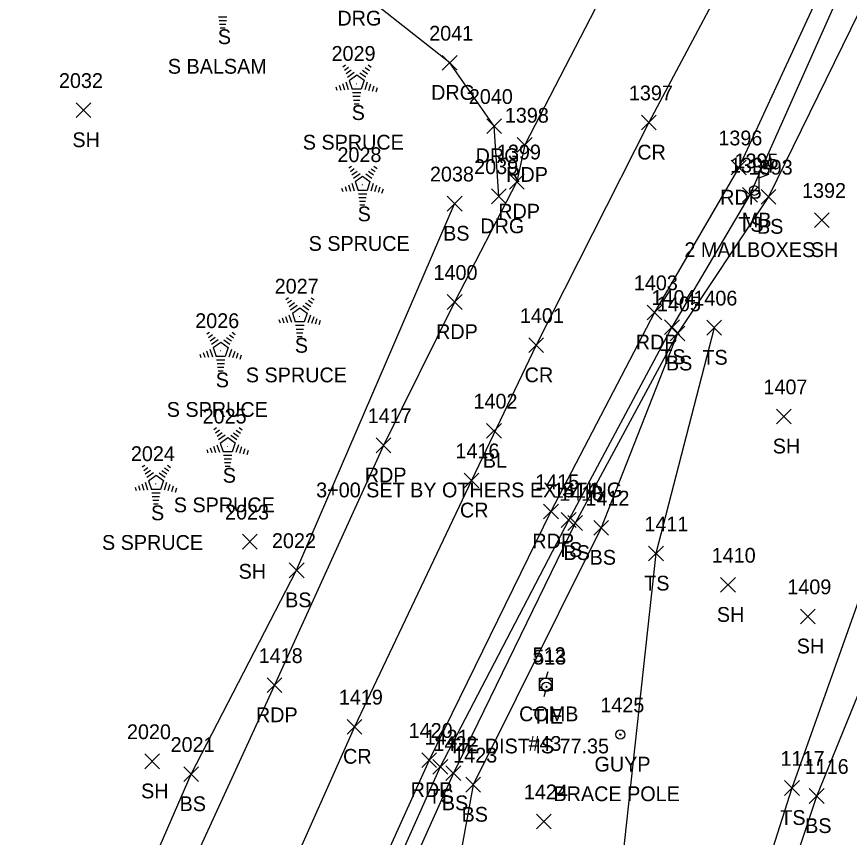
# Model space of a CAD drawing. Extents: x 1885914 to 1887218, y 756253 to 760620.
# Drawn here: x 1886470.3 to 1886583, y 759954.5 to 760065.4 of the extents above; entities that cross this region are included whole.
import ezdxf

# ---------------------------------------------------------------- set-up
doc = ezdxf.new("R2010")
doc.units = 0
for name, color, linetype in [('C_A', 7, 'Continuous'), ('C_C', 7, 'Continuous'), ('C_I', 7, 'Continuous'), ('C_TIC', 7, 'Continuous'), ('CBP', 7, 'Continuous'), ('L_A', 7, 'Continuous'), ('L_C', 7, 'Continuous'), ('L_I', 7, 'Continuous'), ('L_TIC', 7, 'Continuous'), ('LELB', 7, 'Continuous'), ('LMB', 7, 'Continuous'), ('LTC', 7, 'Continuous'), ('P_A', 7, 'Continuous'), ('P_I', 7, 'Continuous'), ('P_TIC', 7, 'Continuous'), ('PET', 7, 'Continuous'), ('PRC', 7, 'Continuous'), ('R_A', 7, 'Continuous'), ('R_I', 7, 'Continuous'), ('R_TIC', 7, 'Continuous'), ('RDG', 7, 'Continuous'), ('U_A', 7, 'Continuous'), ('U_C', 7, 'Continuous'), ('U_I', 7, 'Continuous'), ('UP', 7, 'Continuous'), ('UPGW', 7, 'Continuous')]:
    doc.layers.add(name, color=color, linetype=linetype)

msp = doc.modelspace()

# ---------------------------------------------------------------- linework, layer by layer
at = {"layer": 'C_TIC'}
for points in [[(1886533.9, 760008.44), (1886535.9, 760010.44)], [(1886535.9, 760008.44), (1886533.9, 760010.44)]]:
    msp.add_lwpolyline(points, dxfattribs=at)
at = {"layer": 'CBP'}
for radius in [0.625, 0.0833]:
    msp.add_circle((1886542, 759974.83), radius, dxfattribs=at)
at = {"layer": 'L_TIC'}
for points in [[(1886478.39, 760051.78), (1886480.39, 760053.78)], [(1886480.39, 760051.78), (1886478.39, 760053.78)], [(1886568.53, 760040.34), (1886570.53, 760042.34)], [(1886570.53, 760040.34), (1886568.53, 760042.34)], [(1886571.04, 760040.07), (1886573.04, 760042.07)], [(1886573.04, 760040.07), (1886571.04, 760042.07)], [(1886528.58, 760039.14), (1886530.58, 760041.14)], [(1886530.58, 760039.14), (1886528.58, 760041.14)], [(1886578.26, 760036.92), (1886580.26, 760038.92)], [(1886580.26, 760036.92), (1886578.26, 760038.92)], [(1886557.98, 760022.45), (1886559.98, 760024.45)], [(1886559.98, 760022.45), (1886557.98, 760024.45)], [(1886558.72, 760021.59), (1886560.72, 760023.59)], [(1886560.72, 760021.59), (1886558.72, 760023.59)], [(1886558.72, 760021.59), (1886560.72, 760023.59)], [(1886560.72, 760021.59), (1886558.72, 760023.59)], [(1886563.69, 760022.37), (1886565.69, 760024.37)], [(1886565.69, 760022.37), (1886563.69, 760024.37)], [(1886573.12, 760010.37), (1886575.12, 760012.37)], [(1886575.12, 760010.37), (1886573.12, 760012.37)], [(1886544.01, 759996.38), (1886546.01, 759998.38)], [(1886546.01, 759996.38), (1886544.01, 759998.38)], [(1886544.87, 759995.97), (1886546.87, 759997.97)], [(1886546.87, 759995.97), (1886544.87, 759997.97)], [(1886548.4, 759995.33), (1886550.4, 759997.33)], [(1886550.4, 759995.33), (1886548.4, 759997.33)], [(1886500.87, 759993.44), (1886502.87, 759995.44)], [(1886502.87, 759993.44), (1886500.87, 759995.44)], [(1886555.81, 759991.84), (1886557.81, 759993.84)], [(1886557.81, 759991.84), (1886555.81, 759993.84)], [(1886507.21, 759989.58), (1886509.21, 759991.58)], [(1886509.21, 759989.58), (1886507.21, 759991.58)], [(1886565.56, 759987.61), (1886567.56, 759989.61)], [(1886567.56, 759987.61), (1886565.56, 759989.61)], [(1886576.36, 759983.34), (1886578.36, 759985.34)], [(1886578.36, 759983.34), (1886576.36, 759985.34)], [(1886487.68, 759963.75), (1886489.68, 759965.75)], [(1886489.68, 759963.75), (1886487.68, 759965.75)], [(1886526.64, 759963.02), (1886528.64, 759965.02)], [(1886528.64, 759963.02), (1886526.64, 759965.02)], [(1886492.94, 759962.02), (1886494.94, 759964.02)], [(1886494.94, 759962.02), (1886492.94, 759964.02)], [(1886528.41, 759962.14), (1886530.41, 759964.14)], [(1886530.41, 759962.14), (1886528.41, 759964.14)], [(1886531.08, 759960.59), (1886533.08, 759962.59)], [(1886533.08, 759960.59), (1886531.08, 759962.59)], [(1886574.22, 759960.15), (1886576.22, 759962.15)], [(1886576.22, 759960.15), (1886574.22, 759962.15)], [(1886577.55, 759959.06), (1886579.55, 759961.06)], [(1886579.55, 759959.06), (1886577.55, 759961.06)], [(1886540.64, 759955.62), (1886542.64, 759957.62)], [(1886542.64, 759955.62), (1886540.64, 759957.62)]]:
    msp.add_lwpolyline(points, dxfattribs=at)
at = {"layer": 'LELB'}
for points in [[(1886725.27, 760338.09), (1886712.33, 760310.28), (1886698.46, 760286.41), (1886683.25, 760252.31), (1886665.56, 760220.6), (1886649.26, 760186.3), (1886631.93, 760155.48), (1886614.95, 760123.77), (1886599.48, 760094.94), (1886586.46, 760070.53), (1886572.04, 760041.07), (1886559.72, 760022.59), (1886545.87, 759996.97), (1886529.41, 759963.14), (1886510.6, 759921.25), (1886501.24, 759900.36), (1886492.69, 759872.91), (1886485.39, 759846.95), (1886480.56, 759824.59), (1886476.3, 759808.27), (1886477.13, 759795.21)], [(1886722.34, 760338.16), (1886708.2, 760311.94), (1886695.5, 760287.88), (1886679.14, 760254.71), (1886661.55, 760221.54), (1886644.91, 760188.52), (1886628.61, 760157.02), (1886611.22, 760125.9), (1886595.57, 760097.05), (1886583.24, 760072.24), (1886569.53, 760041.34), (1886558.98, 760023.45), (1886545.01, 759997.38), (1886527.64, 759964.02), (1886508.85, 759921.99)], [(1886569.47, 759932.79), (1886578.55, 759960.06), (1886589.25, 759986.28), (1886598.57, 760012.52), (1886604.77, 760034.06), (1886609.07, 760058.69), (1886625.15, 760085.1), (1886640.42, 760091.38), (1886649.45, 760109.89), (1886661.77, 760128.12), (1886683.78, 760144.02), (1886702.73, 760156.3), (1886717, 760162.7), (1886740.68, 760172.2), (1886760.93, 760185.46), (1886776.22, 760178.86), (1886795.79, 760185.28), (1886813.44, 760184.92), (1886834.73, 760176.46), (1886849.11, 760176.99)], [(1886572.3, 759803.95), (1886568.6, 759823.21), (1886564.73, 759854.7), (1886563.87, 759883.9), (1886566.65, 759905.78), (1886566.1, 759932.48), (1886575.22, 759961.15), (1886584.71, 759987.76), (1886595.18, 760013.31), (1886601.19, 760034.22), (1886605.14, 760059.41), (1886622.97, 760086.15), (1886635.93, 760094.98), (1886646.75, 760112.81), (1886658.85, 760130.9), (1886680.3, 760148.52), (1886699.66, 760159.95), (1886715.31, 760165.82), (1886739.18, 760176.38)], [(1886435.82, 759833.71), (1886443.92, 759843.16), (1886452.31, 759861.14), (1886457.66, 759877.13), (1886463.57, 759888.48), (1886474.59, 759918.53), (1886493.94, 759963.02), (1886508.21, 759990.58), (1886529.58, 760040.14)], [(1886564.69, 760023.37), (1886556.81, 759992.84), (1886551.99, 759948.71), (1886542, 759918.15), (1886528.59, 759884.81), (1886523.26, 759869.7), (1886515.99, 759841.78), (1886514.24, 759821.96)], [(1886559.72, 760022.59), (1886549.4, 759996.33), (1886532.08, 759961.59), (1886524, 759917.34), (1886512.94, 759920.8), (1886504.17, 759899.59), (1886494.61, 759872.13), (1886487.33, 759846.58), (1886481.7, 759824.1), (1886477.83, 759807.91), (1886479.96, 759798.66)]]:
    msp.add_lwpolyline(points, dxfattribs=at)
at = {"layer": 'LMB'}
for p, q in [((1886570.77, 760044.52), (1886572.06, 760044.14)), ((1886570.78, 760041.93), (1886570.77, 760044.52)), ((1886570.77, 760043.62), (1886572.06, 760044.13)), ((1886570.12, 760041.92), (1886570.12, 760041.92))]:
    msp.add_line(p, q, dxfattribs=at)
msp.add_circle((1886570.12, 760041.92), 0.656, dxfattribs=at)
at = {"layer": 'LTC'}
for p, q in [((1886498.79, 760065.37), (1886497.65, 760065.37)), ((1886498.71, 760064.87), (1886497.72, 760064.87)), ((1886498.62, 760064.37), (1886497.79, 760064.37)), ((1886498.54, 760063.87), (1886497.86, 760063.87)), ((1886514.47, 760058.66), (1886514.83, 760058.92)), ((1886514.68, 760058.19), (1886515.21, 760058.58)), ((1886517.5, 760058.55), (1886518.05, 760058.15)), ((1886517.87, 760058.9), (1886518.29, 760058.59)), ((1886514.89, 760057.73), (1886515.6, 760058.24)), ((1886515.1, 760057.26), (1886515.98, 760057.9)), ((1886515.33, 760056.81), (1886516.34, 760057.54)), ((1886516.34, 760057.54), (1886517.34, 760056.82)), ((1886516.76, 760057.85), (1886517.57, 760057.27)), ((1886517.13, 760058.2), (1886517.81, 760057.71)), ((1886513.96, 760056.15), (1886514.17, 760055.5)), ((1886514.42, 760056.37), (1886514.69, 760055.54)), ((1886514.87, 760056.59), (1886515.2, 760055.57)), ((1886515.33, 760056.81), (1886515.71, 760055.61)), ((1886517.34, 760056.82), (1886516.95, 760055.61)), ((1886517.77, 760056.55), (1886517.44, 760055.51)), ((1886518.22, 760056.29), (1886517.93, 760055.41)), ((1886518.66, 760056.04), (1886518.43, 760055.32)), ((1886513.51, 760055.94), (1886513.66, 760055.47)), ((1886516.95, 760055.61), (1886515.71, 760055.61)), ((1886516.91, 760055.11), (1886515.76, 760055.11)), ((1886519.11, 760055.79), (1886518.92, 760055.22)), ((1886516.82, 760054.61), (1886515.83, 760054.61)), ((1886516.74, 760054.11), (1886515.91, 760054.11)), ((1886516.66, 760053.61), (1886515.98, 760053.61)), ((1886515.27, 760044.97), (1886515.62, 760045.23)), ((1886515.48, 760044.51), (1886516.01, 760044.89)), ((1886518.3, 760044.86), (1886518.85, 760044.47)), ((1886518.67, 760045.21), (1886519.09, 760044.91)), ((1886515.69, 760044.04), (1886516.39, 760044.55)), ((1886515.9, 760043.58), (1886516.78, 760044.21)), ((1886516.12, 760043.12), (1886517.13, 760043.85)), ((1886517.13, 760043.85), (1886518.13, 760043.13)), ((1886517.55, 760044.17), (1886518.36, 760043.58)), ((1886517.92, 760044.52), (1886518.6, 760044.02)), ((1886515.21, 760042.68), (1886515.48, 760041.85)), ((1886515.67, 760042.9), (1886516, 760041.88)), ((1886516.12, 760043.12), (1886516.51, 760041.93)), ((1886518.13, 760043.13), (1886517.74, 760041.93)), ((1886518.57, 760042.86), (1886518.23, 760041.82)), ((1886519.01, 760042.61), (1886518.73, 760041.72)), ((1886514.3, 760042.25), (1886514.45, 760041.78)), ((1886514.76, 760042.47), (1886514.97, 760041.82)), ((1886517.74, 760041.93), (1886516.51, 760041.93)), ((1886517.7, 760041.43), (1886516.56, 760041.43)), ((1886519.46, 760042.36), (1886519.22, 760041.63)), ((1886519.9, 760042.11), (1886519.71, 760041.53)), ((1886517.62, 760040.93), (1886516.63, 760040.93)), ((1886517.53, 760040.43), (1886516.7, 760040.43)), ((1886517.45, 760039.93), (1886516.77, 760039.93)), ((1886506.77, 760027.19), (1886507.13, 760027.45)), ((1886506.98, 760026.73), (1886507.51, 760027.11)), ((1886507.19, 760026.26), (1886507.9, 760026.77)), ((1886509.43, 760026.74), (1886510.11, 760026.24)), ((1886509.8, 760027.09), (1886510.35, 760026.69)), ((1886510.17, 760027.43), (1886510.59, 760027.13)), ((1886507.4, 760025.8), (1886508.28, 760026.44)), ((1886507.63, 760025.34), (1886508.64, 760026.08)), ((1886508.64, 760026.08), (1886509.64, 760025.35)), ((1886509.06, 760026.39), (1886509.87, 760025.8)), ((1886506.26, 760024.69), (1886506.47, 760024.04)), ((1886506.72, 760024.91), (1886506.99, 760024.07)), ((1886507.17, 760025.12), (1886507.5, 760024.1)), ((1886507.63, 760025.34), (1886508.01, 760024.15)), ((1886509.64, 760025.35), (1886509.25, 760024.15)), ((1886510.07, 760025.08), (1886509.74, 760024.04)), ((1886510.52, 760024.83), (1886510.23, 760023.95)), ((1886510.96, 760024.58), (1886510.73, 760023.85)), ((1886505.81, 760024.47), (1886505.96, 760024.01)), ((1886509.25, 760024.15), (1886508.01, 760024.15)), ((1886509.21, 760023.65), (1886508.06, 760023.65)), ((1886511.41, 760024.33), (1886511.22, 760023.76)), ((1886496.08, 760022.53), (1886496.44, 760022.79)), ((1886496.29, 760022.06), (1886496.82, 760022.45)), ((1886499.11, 760022.42), (1886499.66, 760022.02)), ((1886499.48, 760022.77), (1886499.9, 760022.47)), ((1886509.12, 760023.15), (1886508.13, 760023.15)), ((1886509.04, 760022.65), (1886508.21, 760022.65)), ((1886496.5, 760021.6), (1886497.21, 760022.11)), ((1886496.71, 760021.13), (1886497.59, 760021.77)), ((1886496.94, 760020.68), (1886497.95, 760021.41)), ((1886497.95, 760021.41), (1886498.94, 760020.69)), ((1886498.37, 760021.73), (1886499.18, 760021.14)), ((1886498.74, 760022.07), (1886499.42, 760021.58)), ((1886508.96, 760022.15), (1886508.28, 760022.15)), ((1886495.57, 760020.03), (1886495.78, 760019.37)), ((1886496.03, 760020.24), (1886496.3, 760019.41)), ((1886496.48, 760020.46), (1886496.81, 760019.44)), ((1886496.94, 760020.68), (1886497.32, 760019.48)), ((1886498.94, 760020.69), (1886498.55, 760019.48)), ((1886499.38, 760020.42), (1886499.04, 760019.38)), ((1886499.83, 760020.17), (1886499.54, 760019.28)), ((1886495.11, 760019.81), (1886495.27, 760019.34)), ((1886498.55, 760019.48), (1886497.32, 760019.48)), ((1886498.51, 760018.98), (1886497.37, 760018.98)), ((1886500.27, 760019.92), (1886500.03, 760019.19)), ((1886500.72, 760019.67), (1886500.53, 760019.09)), ((1886498.43, 760018.48), (1886497.44, 760018.48)), ((1886498.35, 760017.98), (1886497.52, 760017.98)), ((1886498.26, 760017.48), (1886497.59, 760017.48)), ((1886497.03, 760009.63), (1886497.38, 760009.89)), ((1886500.42, 760009.87), (1886500.84, 760009.57)), ((1886497.24, 760009.17), (1886497.77, 760009.55)), ((1886497.45, 760008.7), (1886498.15, 760009.21)), ((1886497.66, 760008.24), (1886498.53, 760008.87)), ((1886499.31, 760008.83), (1886500.12, 760008.24)), ((1886499.68, 760009.18), (1886500.36, 760008.68)), ((1886500.05, 760009.52), (1886500.6, 760009.13)), ((1886497.88, 760007.78), (1886498.89, 760008.52)), ((1886497.88, 760007.78), (1886498.27, 760006.59)), ((1886498.89, 760008.52), (1886499.89, 760007.79)), ((1886499.89, 760007.79), (1886499.5, 760006.59)), ((1886496.06, 760006.91), (1886496.21, 760006.44)), ((1886496.51, 760007.13), (1886496.73, 760006.48)), ((1886496.97, 760007.35), (1886497.24, 760006.51)), ((1886497.43, 760007.56), (1886497.76, 760006.54)), ((1886499.5, 760006.59), (1886498.27, 760006.59)), ((1886500.33, 760007.52), (1886499.99, 760006.48)), ((1886500.77, 760007.27), (1886500.48, 760006.38)), ((1886501.22, 760007.02), (1886500.98, 760006.29)), ((1886501.66, 760006.77), (1886501.47, 760006.19)), ((1886499.46, 760006.09), (1886498.31, 760006.09)), ((1886499.38, 760005.59), (1886498.39, 760005.59)), ((1886487.32, 760004.55), (1886487.68, 760004.8)), ((1886487.53, 760004.08), (1886488.06, 760004.46)), ((1886490.35, 760004.44), (1886490.9, 760004.04)), ((1886490.72, 760004.79), (1886491.14, 760004.48)), ((1886499.29, 760005.09), (1886498.46, 760005.09)), ((1886499.21, 760004.59), (1886498.53, 760004.59)), ((1886487.74, 760003.61), (1886488.45, 760004.13)), ((1886487.95, 760003.15), (1886488.83, 760003.79)), ((1886488.18, 760002.69), (1886489.19, 760003.43)), ((1886489.19, 760003.43), (1886490.19, 760002.7)), ((1886489.61, 760003.74), (1886490.42, 760003.15)), ((1886489.98, 760004.09), (1886490.66, 760003.6)), ((1886486.81, 760002.04), (1886487.02, 760001.39)), ((1886487.27, 760002.26), (1886487.54, 760001.42)), ((1886487.72, 760002.47), (1886488.05, 760001.46)), ((1886488.18, 760002.69), (1886488.56, 760001.5)), ((1886490.19, 760002.7), (1886489.79, 760001.5)), ((1886490.62, 760002.43), (1886490.28, 760001.39)), ((1886491.07, 760002.18), (1886490.78, 760001.3)), ((1886486.36, 760001.83), (1886486.51, 760001.36)), ((1886489.79, 760001.5), (1886488.56, 760001.5)), ((1886489.76, 760001), (1886488.61, 760001)), ((1886491.51, 760001.93), (1886491.27, 760001.2)), ((1886491.96, 760001.68), (1886491.77, 760001.11)), ((1886489.67, 760000.5), (1886488.68, 760000.5)), ((1886489.59, 760000), (1886488.76, 760000)), ((1886489.5, 759999.5), (1886488.83, 759999.5))]:
    msp.add_line(p, q, dxfattribs=at)
at = {"layer": 'P_TIC'}
for points in [[(1886554.85, 760050.11), (1886556.85, 760052.11)], [(1886556.85, 760050.11), (1886554.85, 760052.11)], [(1886538.06, 760047.09), (1886540.06, 760049.09)], [(1886540.06, 760047.09), (1886538.06, 760049.09)], [(1886567, 760044.02), (1886569, 760046.02)], [(1886569, 760044.02), (1886567, 760046.02)], [(1886537, 760042.12), (1886539, 760044.12)], [(1886539, 760042.12), (1886537, 760044.12)], [(1886528.58, 760025.84), (1886530.58, 760027.84)], [(1886530.58, 760025.84), (1886528.58, 760027.84)], [(1886555.6, 760024.44), (1886557.6, 760026.44)], [(1886557.6, 760024.44), (1886555.6, 760026.44)], [(1886539.62, 760020), (1886541.62, 760022)], [(1886541.62, 760020), (1886539.62, 760022)], [(1886518.95, 760006.47), (1886520.95, 760008.47)], [(1886520.95, 760006.47), (1886518.95, 760008.47)], [(1886530.87, 760001.72), (1886532.87, 760003.72)], [(1886532.87, 760001.72), (1886530.87, 760003.72)], [(1886541.61, 759997.54), (1886543.61, 759999.54)], [(1886543.61, 759997.54), (1886541.61, 759999.54)], [(1886504.21, 759974.04), (1886506.21, 759976.04)], [(1886506.21, 759974.04), (1886504.21, 759976.04)], [(1886515.05, 759968.43), (1886517.05, 759970.43)], [(1886517.05, 759968.43), (1886515.05, 759970.43)], [(1886525.14, 759963.92), (1886527.14, 759965.92)], [(1886527.14, 759963.92), (1886525.14, 759965.92)]]:
    msp.add_lwpolyline(points, dxfattribs=at)
at = {"layer": 'PET'}
for points in [[(1886697.38, 760351.34), (1886683.55, 760324.32), (1886670.92, 760299), (1886655.54, 760267.57), (1886637.84, 760233.45), (1886621.76, 760202.26), (1886604.96, 760170.92), (1886588.13, 760139.08), (1886573.73, 760111.63), (1886569.92, 760108.66), (1886558.78, 760086.23), (1886539.06, 760048.09), (1886538, 760043.12), (1886529.58, 760026.84), (1886519.95, 760007.47), (1886505.21, 759975.04), (1886485.32, 759931.76)], [(1886719.61, 760339.51), (1886705.93, 760312.96), (1886693.41, 760288.8), (1886676.56, 760255.91), (1886659.38, 760222.81), (1886642.61, 760189.88), (1886625.62, 760158.68), (1886608.91, 760127.1), (1886594.01, 760097.91), (1886581.16, 760073.4), (1886568, 760045.02), (1886556.6, 760025.44), (1886542.61, 759998.54), (1886526.14, 759964.92), (1886507.07, 759922.75)]]:
    msp.add_lwpolyline(points, dxfattribs=at)
at = {"layer": 'PRC'}
msp.add_lwpolyline([(1886708.51, 760345.16), (1886695.27, 760318.5), (1886682.3, 760293.2), (1886665.98, 760261.32), (1886649.02, 760227.78), (1886632.44, 760196.03), (1886615.49, 760164.09), (1886599.17, 760133.16), (1886583.22, 760103.13), (1886570.57, 760078.83), (1886555.85, 760051.11), (1886540.62, 760021), (1886531.87, 760002.72), (1886516.05, 759969.43), (1886496.99, 759926.69)], dxfattribs=at)
at = {"layer": 'R_TIC'}
for points in [[(1886527.91, 760058.18), (1886529.91, 760060.18)], [(1886529.91, 760058.18), (1886527.91, 760060.18)], [(1886533.93, 760049.62), (1886535.93, 760051.62)], [(1886535.93, 760049.62), (1886533.93, 760051.62)], [(1886534.57, 760040.14), (1886536.57, 760042.14)], [(1886536.57, 760040.14), (1886534.57, 760042.14)]]:
    msp.add_lwpolyline(points, dxfattribs=at)
at = {"layer": 'RDG'}
msp.add_lwpolyline([(1886535.57, 760041.14), (1886534.93, 760050.62), (1886528.91, 760059.18), (1886516.23, 760069.22), (1886491.88, 760084.76), (1886462.81, 760103.73), (1886439.22, 760117.89), (1886425.17, 760124.99), (1886402.51, 760125.72), (1886387.36, 760112.61), (1886362.97, 760090.43), (1886346.71, 760087.42)], dxfattribs=at)
at = {"layer": 'UP'}
for p, q in [((1886542.17, 759976.84), (1886541.92, 759976)), ((1886541.08, 759974.34), (1886541.08, 759976)), ((1886541.08, 759976), (1886542.75, 759976)), ((1886541.92, 759975.17), (1886541.92, 759975.17)), ((1886542.75, 759976), (1886542.75, 759974.34)), ((1886542.75, 759974.34), (1886541.08, 759974.34)), ((1886541.67, 759973.5), (1886541.92, 759974.34))]:
    msp.add_line(p, q, dxfattribs=at)
msp.add_circle((1886541.92, 759975.17), 0.833, dxfattribs=at)
at = {"layer": 'UPGW'}
for radius in [0.625, 0.0833]:
    msp.add_circle((1886551.99, 759968.37), radius, dxfattribs=at)

# ---------------------------------------------------------------- texts
at = {"layer": 'C_A'}
for s, p in [('BL', (1886533.39, 760004.44)), ('TIE', (1886540.08, 759969.83))]:
    msp.add_text(s, height=2, dxfattribs=at).set_placement(p)
at = {"layer": 'C_C'}
for s, p in [('3+00 SET BY OTHERS EXISTING', (1886510.85, 760000.44)), ('TIE DIST IS 77.35', (1886528.76, 759965.83))]:
    msp.add_text(s, height=2, dxfattribs=at).set_placement(p)
at = {"layer": 'C_I'}
for s, p in [('1402', (1886532.13, 760012.44)), ('513', (1886540.21, 759977.83))]:
    msp.add_text(s, height=2, dxfattribs=at).set_placement(p)
at = {"layer": 'L_A'}
for s, p in [('S', (1886497.55, 760061.71)), ('S', (1886515.66, 760051.45)), ('SH', (1886477.88, 760047.78)), ('S', (1886516.46, 760037.76)), ('TS', (1886567.94, 760036.34)), ('MB', (1886568.43, 760036.92)), ('BS', (1886570.48, 760036.07)), ('BS', (1886528.02, 760035.14)), ('SH', (1886577.75, 760032.92)), ('S', (1886507.97, 760019.99)), ('TS', (1886557.39, 760018.45)), ('TS', (1886563.1, 760018.37)), ('BS', (1886558.16, 760017.59)), ('BS', (1886558.16, 760017.59)), ('S', (1886497.27, 760015.32)), ('SH', (1886572.61, 760006.37)), ('S', (1886498.22, 760002.42)), ('S', (1886488.51, 759997.34)), ('TS', (1886543.42, 759992.38)), ('BS', (1886544.31, 759991.97)), ('BS', (1886547.84, 759991.33)), ('SH', (1886500.36, 759989.44)), ('TS', (1886555.22, 759987.84)), ('BS', (1886506.65, 759985.58)), ('SH', (1886565.05, 759983.61)), ('SH', (1886575.85, 759979.34)), ('SH', (1886487.17, 759959.75)), ('TS', (1886526.05, 759959.02)), ('BS', (1886492.38, 759958.02)), ('BS', (1886527.85, 759958.14)), ('BS', (1886530.52, 759956.59)), ('TS', (1886573.63, 759956.15)), ('BS', (1886576.99, 759955.06))]:
    msp.add_text(s, height=2, dxfattribs=at).set_placement(p)
at = {"layer": 'L_C'}
for s, p in [('S BALSAM', (1886490.79, 760057.71)), ('S SPRUCE', (1886509.04, 760047.45)), ('S SPRUCE', (1886509.83, 760033.76)), ('2 MAILBOXES', (1886560.66, 760032.92)), ('S SPRUCE', (1886501.34, 760015.99)), ('S SPRUCE', (1886490.64, 760011.32)), ('S SPRUCE', (1886491.59, 759998.42)), ('S SPRUCE', (1886481.88, 759993.34))]:
    msp.add_text(s, height=2, dxfattribs=at).set_placement(p)
at = {"layer": 'L_I'}
for s, p in [('2029', (1886512.93, 760059.45)), ('2032', (1886476.06, 760055.78)), ('2028', (1886513.73, 760045.76)), ('1394', (1886566.83, 760044.34)), ('1395', (1886567.43, 760044.92)), ('1393', (1886569.35, 760044.07)), ('2038', (1886526.24, 760043.14)), ('1392', (1886576.57, 760040.92)), ('2027', (1886505.24, 760027.99)), ('1404', (1886556.21, 760026.45)), ('1406', (1886561.87, 760026.37)), ('1405', (1886556.94, 760025.59)), ('1405', (1886556.94, 760025.59)), ('2026', (1886494.49, 760023.32)), ('1407', (1886571.35, 760014.37)), ('2025', (1886495.49, 760010.42)), ('2024', (1886485.79, 760005.34)), ('1414', (1886542.88, 760000.38)), ('1413', (1886543.74, 759999.97)), ('1412', (1886547.27, 759999.33)), ('2023', (1886498.53, 759997.44)), ('1411', (1886555.25, 759995.84)), ('2022', (1886504.87, 759993.58)), ('1410', (1886564.35, 759991.61)), ('1409', (1886574.58, 759987.34)), ('2020', (1886485.26, 759967.75)), ('1421', (1886525.51, 759967.02)), ('1422', (1886526.71, 759966.14)), ('2021', (1886491.16, 759966.02)), ('1423', (1886529.39, 759964.59)), ('1117', (1886573.66, 759964.15)), ('1116', (1886576.93, 759963.06)), ('1424', (1886538.94, 759959.62))]:
    msp.add_text(s, height=2, dxfattribs=at).set_placement(p)
at = {"layer": 'LTC'}
for p in [(1886516.22, 760056.55), (1886517.02, 760042.87), (1886508.52, 760025.09), (1886497.83, 760020.43), (1886498.77, 760007.53), (1886489.07, 760002.44)]:
    msp.add_text('.', height=1.04, rotation=270, dxfattribs=at).set_placement(p)
at = {"layer": 'P_A'}
for s, p in [('CR', (1886554.28, 760046.11)), ('RDP', (1886536.55, 760043.09)), ('RDP', (1886565.49, 760040.02)), ('RDP', (1886535.48, 760038.12)), ('RDP', (1886527.07, 760021.84)), ('RDP', (1886554.08, 760020.44)), ('CR', (1886539.05, 760016)), ('RDP', (1886517.43, 760002.47)), ('CR', (1886530.3, 759997.72)), ('RDP', (1886540.09, 759993.54)), ('RDP', (1886502.7, 759970.04)), ('CR', (1886514.49, 759964.43)), ('RDP', (1886523.63, 759959.92))]:
    msp.add_text(s, height=2, dxfattribs=at).set_placement(p)
at = {"layer": 'P_I'}
for s, p in [('1397', (1886553.15, 760054.11)), ('1398', (1886536.37, 760051.09)), ('1396', (1886565.25, 760048.02)), ('1399', (1886535.3, 760046.12)), ('1400', (1886526.72, 760029.84)), ('1403', (1886553.82, 760028.44)), ('1401', (1886538.41, 760024)), ('1417', (1886517.82, 760010.47)), ('1416', (1886529.69, 760005.72)), ('1415', (1886540.48, 760001.54)), ('1418', (1886503.08, 759978.04)), ('1419', (1886513.92, 759972.43)), ('1420', (1886523.36, 759967.92))]:
    msp.add_text(s, height=2, dxfattribs=at).set_placement(p)
at = {"layer": 'R_A'}
for p in [(1886513.72, 760064.22), (1886526.4, 760054.18), (1886532.42, 760045.62), (1886533.06, 760036.14)]:
    msp.add_text('DRG', height=2, dxfattribs=at).set_placement(p)
at = {"layer": 'R_I'}
for s, p in [('2041', (1886526.14, 760062.18)), ('2040', (1886531.5, 760053.62)), ('2039', (1886532.22, 760044.14))]:
    msp.add_text(s, height=2, dxfattribs=at).set_placement(p)
at = {"layer": 'U_A'}
for s, p in [('COMB', (1886538.3, 759970.17)), ('GUYP', (1886548.5, 759963.37))]:
    msp.add_text(s, height=2, dxfattribs=at).set_placement(p)
at = {"layer": 'U_C'}
for s, p in [('#43', (1886539.56, 759966.17)), ('BRACE POLE', (1886542.95, 759959.37))]:
    msp.add_text(s, height=2, dxfattribs=at).set_placement(p)
at = {"layer": 'U_I'}
for s, p in [('512', (1886540.12, 759978.17)), ('1425', (1886549.29, 759971.37))]:
    msp.add_text(s, height=2, dxfattribs=at).set_placement(p)

doc.saveas('drawing.dxf')
